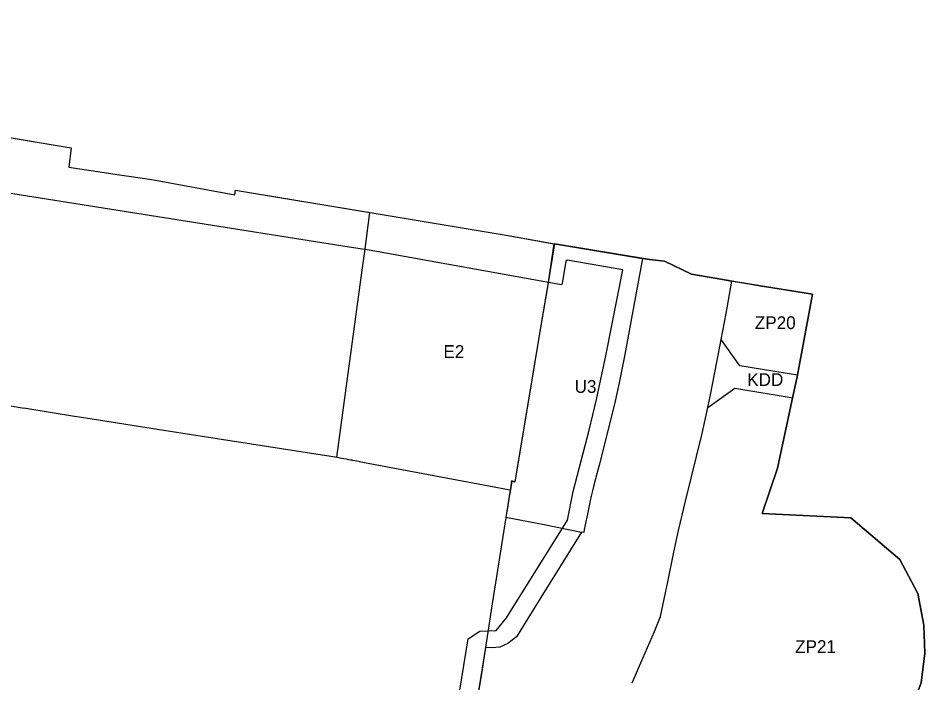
# Model space of a CAD drawing. Extents: x 7428103 to 7431580, y 5545880 to 5549002.
# Drawn here: x 7430217.3 to 7430610.6, y 5548705.9 to 5548994.5 of the extents above; entities that cross this region are included whole.
import ezdxf

# ---------------------------------------------------------------- set-up
doc = ezdxf.new("R2010")
doc.units = 0
for name, color, linetype in [('CZ_L_granica obszaru objętego planem', 7, 'Continuous'), ('CZ_L_linie rozgraniczające tereny o różnym przeznaczeniu oraz różnych warunkach ich zabudowy i zagospodarowania', 7, 'Continuous'), ('CZ_L_maksymalne nieprzekraczalne linie zabudowy', 7, 'Continuous'), ('CZ_L_opisy_linie rozgraniczające tereny o różnym przeznaczeniu oraz różnych warunkach ich zabudowy i zagospodarowania', 7, 'Continuous'), ('Łąki_Nowohuckie', 7, 'Continuous')]:
    doc.layers.add(name, color=color, linetype=linetype)

msp = doc.modelspace()

# ---------------------------------------------------------------- linework, layer by layer
at = {"layer": 'CZ_L_granica obszaru objętego planem'}
for p, q in [((7430086.49, 5548963.83), (7430240.28, 5548938.14)), ((7430240.28, 5548938.14), (7430239.23, 5548929.76)), ((7430239.23, 5548929.76), (7430261.25, 5548926.5)), ((7430261.25, 5548926.5), (7430275.34, 5548924.41)), ((7430275.34, 5548924.41), (7430311.25, 5548917.71)), ((7430311.25, 5548917.71), (7430311.61, 5548919.78)), ((7430311.61, 5548919.78), (7430370, 5548910.05)), ((7430370, 5548910.05), (7430429.86, 5548900.05)), ((7430429.86, 5548900.05), (7430449.96, 5548896.44)), ((7430449.96, 5548896.44), (7430491.11, 5548889.67)), ((7430491.11, 5548889.67), (7430497.73, 5548888.99)), ((7430497.73, 5548888.99), (7430509.45, 5548883.29)), ((7430509.45, 5548883.29), (7430519.62, 5548881.57)), ((7430519.62, 5548881.57), (7430541.01, 5548877.97)), ((7430541.01, 5548877.97), (7430561.92, 5548874.58)), ((7430561.92, 5548874.58), (7430555.2, 5548838.75)), ((7430555.2, 5548838.75), (7430553.33, 5548830.28)), ((7430553.33, 5548830.28), (7430546.69, 5548799.05)), ((7430546.69, 5548799.05), (7430540.02, 5548779.43)), ((7430540.02, 5548779.43), (7430578.55, 5548777.58)), ((7430578.55, 5548777.58), (7430599.74, 5548759.48)), ((7430599.74, 5548759.48), (7430607.53, 5548744.68)), ((7430607.53, 5548744.68), (7430610.23, 5548730.92)), ((7430610.23, 5548730.92), (7430610.64, 5548718.74)), ((7430610.64, 5548718.74), (7430609.07, 5548705.89)), ((7430609.07, 5548705.89), (7430607.9, 5548702.9))]:
    msp.add_line(p, q, dxfattribs=at)
at = {"layer": 'CZ_L_linie rozgraniczające tereny o różnym przeznaczeniu oraz różnych warunkach ich zabudowy i zagospodarowania'}
for p, q in [((7430367.62, 5548893.18), (7430369.8, 5548910.09)), ((7430449.68, 5548896.49), (7430447.18, 5548879.79)), ((7430366.58, 5548885.1), (7430367.62, 5548893.18)), ((7430488.13, 5548890.16), (7430480.4, 5548847.76)), ((7430364.98, 5548873.36), (7430366.58, 5548885.1)), ((7430447.16, 5548879.67), (7430444.04, 5548861)), ((7430447.18, 5548879.79), (7430447.16, 5548879.67)), ((7430524.37, 5548866.26), (7430526.89, 5548880.35)), ((7430355.46, 5548803.84), (7430364.98, 5548873.36)), ((7430522.2, 5548854.91), (7430524.37, 5548866.26)), ((7430444.04, 5548861), (7430441.42, 5548845.37)), ((7430520.33, 5548845.12), (7430522.2, 5548854.91)), ((7430530.43, 5548843.49), (7430522.2, 5548854.91)), ((7430480.4, 5548847.76), (7430477.95, 5548836.13)), ((7430441.42, 5548845.37), (7430432.69, 5548793.21)), ((7430518.49, 5548835.46), (7430520.33, 5548845.12)), ((7430555.33, 5548839.46), (7430530.43, 5548843.49)), ((7430477.95, 5548836.13), (7430476.27, 5548828.15)), ((7430517.77, 5548831.68), (7430518.49, 5548835.46)), ((7430516.42, 5548825.44), (7430528.22, 5548833.76)), ((7430516.42, 5548825.44), (7430517.77, 5548831.68)), ((7430528.22, 5548833.76), (7430552.61, 5548829.77)), ((7430476.27, 5548828.15), (7430473.17, 5548815.37)), ((7430552.61, 5548829.77), (7430553.2, 5548829.66)), ((7430214.13, 5548826.1), (7430217.3, 5548825.6)), ((7430217.3, 5548825.6), (7430219.04, 5548825.32)), ((7430219.04, 5548825.32), (7430220.57, 5548825.08)), ((7430220.57, 5548825.08), (7430241.79, 5548821.74)), ((7430514.01, 5548814.2), (7430516.42, 5548825.44)), ((7430241.79, 5548821.74), (7430246.7, 5548820.97)), ((7430246.7, 5548820.97), (7430280.49, 5548815.65)), ((7430280.49, 5548815.65), (7430303.63, 5548812.01)), ((7430473.17, 5548815.37), (7430469.31, 5548800.35)), ((7430303.63, 5548812.01), (7430352.86, 5548804.26)), ((7430506.73, 5548784.73), (7430514.01, 5548814.2)), ((7430352.86, 5548804.26), (7430354.69, 5548803.98)), ((7430354.69, 5548803.98), (7430354.74, 5548803.96)), ((7430354.74, 5548803.96), (7430354.79, 5548803.96)), ((7430354.79, 5548803.96), (7430355.46, 5548803.84)), ((7430355.46, 5548803.84), (7430355.6, 5548803.81)), ((7430355.6, 5548803.81), (7430357.52, 5548803.47)), ((7430357.52, 5548803.47), (7430359.56, 5548803.1)), ((7430359.56, 5548803.1), (7430360.74, 5548802.88)), ((7430360.74, 5548802.88), (7430361.6, 5548802.72)), ((7430361.6, 5548802.72), (7430361.82, 5548802.68)), ((7430361.82, 5548802.68), (7430361.95, 5548802.65)), ((7430361.95, 5548802.65), (7430362.07, 5548802.63)), ((7430362.07, 5548802.63), (7430362.54, 5548802.55)), ((7430362.54, 5548802.55), (7430363.27, 5548802.41)), ((7430363.27, 5548802.41), (7430363.41, 5548802.39)), ((7430363.41, 5548802.39), (7430364.09, 5548802.26)), ((7430364.09, 5548802.26), (7430364.12, 5548802.25)), ((7430364.12, 5548802.25), (7430364.12, 5548802.25)), ((7430364.12, 5548802.25), (7430364.15, 5548802.25)), ((7430364.15, 5548802.25), (7430365.12, 5548802.07)), ((7430365.12, 5548802.07), (7430365.2, 5548802.05)), ((7430365.2, 5548802.05), (7430430.79, 5548789.72)), ((7430469.31, 5548800.34), (7430467.24, 5548792.28)), ((7430469.31, 5548800.35), (7430469.31, 5548800.34)), ((7430431.38, 5548793.6), (7430430.88, 5548790.32)), ((7430432.69, 5548793.21), (7430431.38, 5548793.6)), ((7430467.24, 5548792.28), (7430466.46, 5548789.24)), ((7430430.79, 5548789.72), (7430429.54, 5548781.86)), ((7430430.83, 5548789.98), (7430430.79, 5548789.72)), ((7430431.01, 5548790.3), (7430430.83, 5548789.98)), ((7430430.88, 5548790.32), (7430431.01, 5548790.3)), ((7430466.18, 5548788.13), (7430465.88, 5548786.96)), ((7430466.46, 5548789.24), (7430466.18, 5548788.13)), ((7430465.26, 5548784.12), (7430464.98, 5548782.76)), ((7430465.35, 5548784.44), (7430465.26, 5548784.12)), ((7430465.71, 5548786.23), (7430465.35, 5548784.44)), ((7430465.79, 5548786.51), (7430465.71, 5548786.23)), ((7430465.8, 5548786.6), (7430465.79, 5548786.51)), ((7430465.86, 5548786.82), (7430465.8, 5548786.6)), ((7430465.87, 5548786.93), (7430465.86, 5548786.82)), ((7430465.88, 5548786.96), (7430465.87, 5548786.93)), ((7430503.83, 5548771.98), (7430506.73, 5548784.73)), ((7430429.53, 5548781.86), (7430428.9, 5548777.83)), ((7430429.54, 5548781.86), (7430429.53, 5548781.86)), ((7430464.98, 5548782.76), (7430464.24, 5548779.08)), ((7430428.9, 5548777.83), (7430445.46, 5548774.58)), ((7430464.24, 5548779.08), (7430463.32, 5548774.54)), ((7430445.46, 5548774.58), (7430461.64, 5548771.34)), ((7430462.89, 5548772.4), (7430462.66, 5548771.28)), ((7430463.31, 5548774.46), (7430462.89, 5548772.4)), ((7430463.32, 5548774.54), (7430463.31, 5548774.46)), ((7430501.56, 5548761.84), (7430503.83, 5548771.98)), ((7430461.64, 5548771.34), (7430443.3, 5548741.72)), ((7430462.63, 5548771.14), (7430461.64, 5548771.34)), ((7430462.66, 5548771.28), (7430462.63, 5548771.14)), ((7430499.08, 5548749.67), (7430501.56, 5548761.84)), ((7430495.9, 5548734.74), (7430499.08, 5548749.67)), ((7430443.3, 5548741.72), (7430433.46, 5548725.82)), ((7430493.28, 5548728.11), (7430495.9, 5548734.74)), ((7430433.46, 5548725.82), (7430429.7, 5548723.04)), ((7430488.33, 5548716.66), (7430493.28, 5548728.11)), ((7430419.97, 5548721.18), (7430417.12, 5548703.26)), ((7430422.81, 5548721.07), (7430419.97, 5548721.18)), ((7430426.2, 5548721.37), (7430422.81, 5548721.07)), ((7430429.7, 5548723.04), (7430426.2, 5548721.37)), ((7430483.68, 5548705.85), (7430488.33, 5548716.66))]:
    msp.add_line(p, q, dxfattribs=at)
for points in [[(7429858.27, 5548994.49), (7429870.98, 5548993.64), (7429898.69, 5548992.61), (7429913.85, 5548991.37), (7429927.18, 5548991.72), (7430074.1, 5548966), (7430086.49, 5548963.83), (7430240.28, 5548938.14), (7430239.23, 5548929.76), (7430261.25, 5548926.5), (7430275.34, 5548924.41), (7430311.25, 5548917.71), (7430311.61, 5548919.78), (7430369.8, 5548910.09)], [(7430369.8, 5548910.09), (7430370, 5548910.05), (7430429.86, 5548900.05), (7430449.68, 5548896.49)], [(7430449.68, 5548896.49), (7430449.96, 5548896.44), (7430488.13, 5548890.16)], [(7430488.13, 5548890.16), (7430491.11, 5548889.67), (7430497.73, 5548888.99), (7430509.45, 5548883.29), (7430519.62, 5548881.57), (7430526.89, 5548880.35)], [(7430555.33, 5548839.46), (7430561.92, 5548874.58), (7430541.01, 5548877.97), (7430526.89, 5548880.35)], [(7430555.33, 5548839.46), (7430555.2, 5548838.75), (7430553.33, 5548830.28), (7430553.2, 5548829.66)], [(7430553.2, 5548829.66), (7430546.69, 5548799.05), (7430540.02, 5548779.43), (7430578.55, 5548777.58), (7430599.74, 5548759.48), (7430607.53, 5548744.68), (7430610.23, 5548730.92), (7430610.64, 5548718.74), (7430609.07, 5548705.89), (7430607.9, 5548702.9), (7430605.76, 5548696.33), (7430596.53, 5548685.05), (7430587.74, 5548680.53), (7430567.94, 5548675.2), (7430560.91, 5548658.77)]]:
    msp.add_lwpolyline(points, dxfattribs=at)
at = {"layer": 'CZ_L_maksymalne nieprzekraczalne linie zabudowy'}
msp.add_lwpolyline([(7430391.51, 5548595.78), (7430412.55, 5548725.02), (7430417.58, 5548728.38), (7430424.59, 5548728.66), (7430429.14, 5548734.14), (7430455.55, 5548776.54), (7430458.13, 5548788.94), (7430464.96, 5548815.57), (7430468.23, 5548828.93), (7430472.39, 5548848.55), (7430479.63, 5548885.23), (7430455.53, 5548889.43), (7430454.82, 5548889), (7430453.23, 5548879.21), (7430452.99, 5548878.7), (7430369.49, 5548893.72), (7430360.94, 5548895.1), (7430108.03, 5548935.09)], dxfattribs=at)
at = {"layer": 'Łąki_Nowohuckie'}
for p, q in [((7430449.96, 5548896.44), (7430447.17, 5548879.57)), ((7430491.11, 5548889.67), (7430449.96, 5548896.44)), ((7430497.73, 5548888.99), (7430491.11, 5548889.67)), ((7430509.45, 5548883.29), (7430497.73, 5548888.99)), ((7430519.62, 5548881.57), (7430509.45, 5548883.29)), ((7430561.9, 5548874.49), (7430541.02, 5548877.87)), ((7430555.2, 5548838.75), (7430561.9, 5548874.49)), ((7430441.43, 5548845.27), (7430432.69, 5548793.06)), ((7430553.33, 5548830.28), (7430555.2, 5548838.75)), ((7430546.69, 5548799.05), (7430553.33, 5548830.28)), ((7430540.02, 5548779.43), (7430546.69, 5548799.05)), ((7430431.39, 5548793.5), (7430430.84, 5548789.88)), ((7430432.69, 5548793.06), (7430431.39, 5548793.5)), ((7430430.84, 5548789.88), (7430430.2, 5548785.94)), ((7430430.2, 5548785.94), (7430428.91, 5548777.73)), ((7430578.55, 5548777.58), (7430540.02, 5548779.43)), ((7430428.91, 5548777.73), (7430422.44, 5548737.45)), ((7430599.74, 5548759.48), (7430578.55, 5548777.58)), ((7430607.53, 5548744.68), (7430599.74, 5548759.48)), ((7430610.23, 5548730.92), (7430607.53, 5548744.68)), ((7430610.64, 5548718.74), (7430610.23, 5548730.92)), ((7430609.07, 5548705.89), (7430610.64, 5548718.74)), ((7430418.24, 5548710), (7430411.55, 5548668.68)), ((7430607.9, 5548702.9), (7430609.07, 5548705.89))]:
    msp.add_line(p, q, dxfattribs=at)
for points in [[(7430447.17, 5548879.57), (7430444.05, 5548860.9), (7430441.43, 5548845.27)], [(7430541.02, 5548877.87), (7430540.99, 5548877.88), (7430519.62, 5548881.57)], [(7430422.44, 5548737.45), (7430421.36, 5548729.8), (7430418.24, 5548710)]]:
    msp.add_lwpolyline(points, dxfattribs=at)

# ---------------------------------------------------------------- texts
at = {"layer": 'CZ_L_opisy_linie rozgraniczające tereny o różnym przeznaczeniu oraz różnych warunkach ich zabudowy i zagospodarowania'}
for s, p in [('ZP20', (7430536.87, 5548859.48)), ('E2', (7430401.78, 5548846.96)), ('KDD', (7430533.57, 5548834.78)), ('U3', (7430458.68, 5548831.78)), ('ZP21', (7430554.35, 5548718.86))]:
    msp.add_text(s, height=5.549, dxfattribs=at).set_placement(p)

doc.saveas('drawing.dxf')
